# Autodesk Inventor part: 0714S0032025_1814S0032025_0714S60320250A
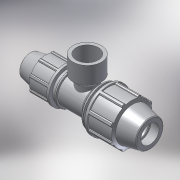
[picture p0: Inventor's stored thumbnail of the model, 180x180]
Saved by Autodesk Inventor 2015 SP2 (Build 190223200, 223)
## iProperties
Created: 2017-02
Part Number: 0714S0032025_1814S0032025_0714S60320250A
Material: PVC-Piping
Description: PLASSON REDUCING TEE FEMALE 32-1"-25
Document SubType Name: Modeling
Designer: KIM
Mass: 92.6774 g
Surface Area: 199.44 cm^2
Volume: 66.1981 cm^3
Density: 1.4 g/cm^3
Appearance: Smooth - White
Author: KIM
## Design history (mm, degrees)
derived "0714S0.ipt"
feature "Solid1::0714S0.ipt"
feature "Solid2::0714S0.ipt"
tag "TaggingFeature1"
body "Solid1"
body "Solid2"
other parameters: "d2" = 32, "d4" = 14.08333, "d5" = 24.14286, "d7" = 64, "d9" = 24.14286, "d11" = 2.41429, "d12" = 51.2, "d13" = 120 deg, "d14" = 48, "d15" = 12 deg, "d16" = 57.6, "d18" = 1.6, "d19" = 35 deg, "d20" = 17.5 deg, "d21" = 59.52, "d23" = 0, "d25" = 360 deg, "d27" = 1.28, "d42" = 37.18, "d46" = 0.96, "d51" = 169, "d53" = 12 deg, "d54" = 67, "d56" = 37.5, "d57" = 25, "d58" = 28.8, "d59" = 22.5, "d60" = 48.6, "d61" = 43.2, "d62" = 21.125, "d63" = 30.42, "d64" = 120 deg, "d65" = 54, "d68" = 12.07143, "d74" = 50.22, "d75" = 35 deg, "d76" = 17.5 deg, "d78" = 0, "d80" = 360 deg, "d85" = 1.08, "d88" = 0.5, "d93" = 58, "d107" = 3.6, "d108" = 0, "d109" = 3.6, "d110" = 0, "d112" = 5.07, "d113" = 45 deg, "d114" = 30.291, "d115" = 58, "d116" = 22, "d117" = 22.5, "d118" = 39.3783, "d119" = 135 deg, "d120" = 4.54365, "d122" = 91, "d123" = 5.07, "d125" = 0, "d127" = 0, "d_" = 32, "E_" = 64, "H_" = 169, "l_" = 67, "d_1" = 25, "E_1" = 54, "l_1" = 58, "L_" = 91, "l_2" = 22, "A_" = 58, "Rp_" = 30.291
